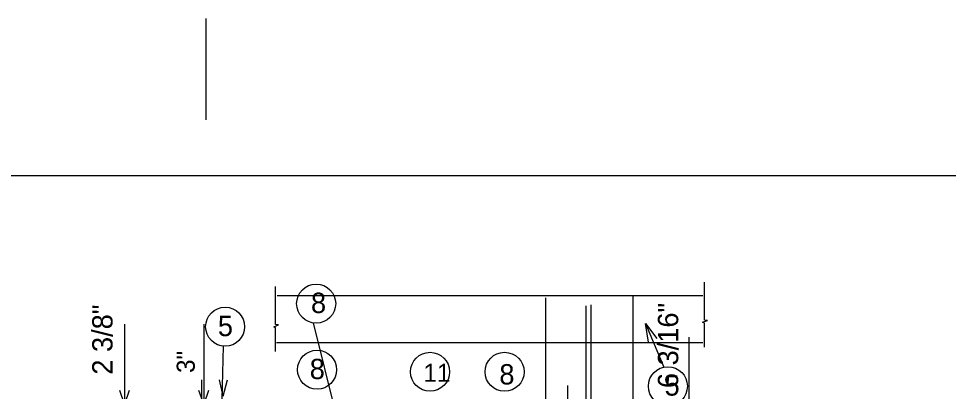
# Model space of a CAD drawing. Extents: x 1509.2 to 1521.3, y 1506 to 1514.6.
# Drawn here: x 1515.051 to 1517.194, y 1513.434 to 1514.293 of the extents above; entities that cross this region are included whole.
import ezdxf

# ---------------------------------------------------------------- set-up
doc = ezdxf.new("R2010")
doc.units = 0
for name, color, linetype in [('Level 1', 7, 'Continuous'), ('Level 3', 7, 'Continuous'), ('Level 37', 7, 'Continuous'), ('Level 4', 7, 'Continuous')]:
    doc.layers.add(name, color=color, linetype=linetype)

msp = doc.modelspace()

# ---------------------------------------------------------------- linework, layer by layer
at = {"layer": 'Level 1'}
msp.add_line((1520.7124, 1513.9308), (1510.2539, 1513.9308), dxfattribs=at)
at = {"layer": 'Level 3'}
for p, q in [((1515.2946, 1513.5887), (1515.2946, 1513.4043)), ((1515.7816, 1513.3841), (1515.7304, 1513.5918)), ((1516.5953, 1513.5593), (1516.5953, 1513.2603)), ((1515.5221, 1513.5383), (1515.5149, 1513.2473)), ((1515.4727, 1513.3884), (1515.4727, 1513.4606)), ((1515.5221, 1513.4232), (1515.5137, 1513.4609)), ((1515.5221, 1513.4232), (1515.5324, 1513.4604)), ((1516.3165, 1513.3842), (1516.3165, 1513.4478))]:
    msp.add_line(p, q, dxfattribs=at)
msp.add_lwpolyline([(1515.3055, 1513.4359), (1515.2946, 1513.4043), (1515.2836, 1513.4359)], dxfattribs=at)
for centre in [(1515.7364, 1513.6363), (1515.5266, 1513.5831)]:
    msp.add_circle(centre, 0.045, dxfattribs=at)
at = {"layer": 'Level 37'}
msp.add_line((1515.4831, 1514.0601), (1515.4831, 1514.2935), dxfattribs=at)
at = {"layer": 'Level 4'}
for p, q in [((1515.6468, 1513.6548), (1516.6279, 1513.6548)), ((1516.2646, 1513.6499), (1516.2646, 1513.5481)), ((1516.4661, 1513.6548), (1516.4661, 1513.6499)), ((1516.4661, 1513.6499), (1516.4661, 1513.5481)), ((1516.3584, 1512.5363), (1516.3584, 1513.6313)), ((1516.37, 1512.5363), (1516.37, 1513.6333)), ((1515.4773, 1513.5887), (1515.4773, 1513.4043)), ((1516.4953, 1513.5903), (1516.538, 1513.4897)), ((1515.6448, 1513.5465), (1516.6279, 1513.5465)), ((1516.2646, 1513.5481), (1516.2646, 1513.3278)), ((1516.4661, 1513.5481), (1516.4661, 1513.3278))]:
    msp.add_line(p, q, dxfattribs=at)
for points in [[(1516.6312, 1513.5361), (1516.6312, 1513.5912), (1516.627, 1513.5933), (1516.6383, 1513.5974), (1516.6312, 1513.5981), (1516.6312, 1513.686)], [(1515.6427, 1513.5258), (1515.6427, 1513.5808), (1515.6385, 1513.583), (1515.6498, 1513.5871), (1515.6427, 1513.5878), (1515.6427, 1513.6757)], [(1516.502, 1513.5478), (1516.4953, 1513.5903), (1516.5212, 1513.556)], [(1515.4883, 1513.4359), (1515.4773, 1513.4043), (1515.4663, 1513.4359)]]:
    msp.add_lwpolyline(points, dxfattribs=at)
for centre in [(1515.7385, 1513.484), (1515.9988, 1513.4791), (1516.1706, 1513.4791), (1516.547, 1513.4459)]:
    msp.add_circle(centre, 0.045, dxfattribs=at)

# ---------------------------------------------------------------- texts
at = {"layer": 'Level 3'}
for s, height, rotation, p in [('8', 0.0469, 0, (1515.7244, 1513.6146)), ('2 3/8"', 0.04687, 90, (1515.2671, 1513.4725)), ('6 3/16"', 0.04687, 90, (1516.5709, 1513.4416)), ('5', 0.0469, 0, (1515.5098, 1513.5613))]:
    msp.add_text(s, height=height, rotation=rotation, dxfattribs=at).set_placement(p)
at = {"layer": 'Level 4'}
for s, height, rotation, p in [('3"', 0.04167, 90, (1515.4566, 1513.4765)), ('8', 0.0469, 0, (1515.7216, 1513.4622)), ('8', 0.0469, 0, (1516.1586, 1513.4499)), ('5', 0.0469, 0, (1516.5394, 1513.4242))]:
    msp.add_text(s, height=height, rotation=rotation, dxfattribs=at).set_placement(p)
msp.add_text('11', height=0.04167, dxfattribs=at).set_placement((1515.9837, 1513.456))

doc.saveas('drawing.dxf')
